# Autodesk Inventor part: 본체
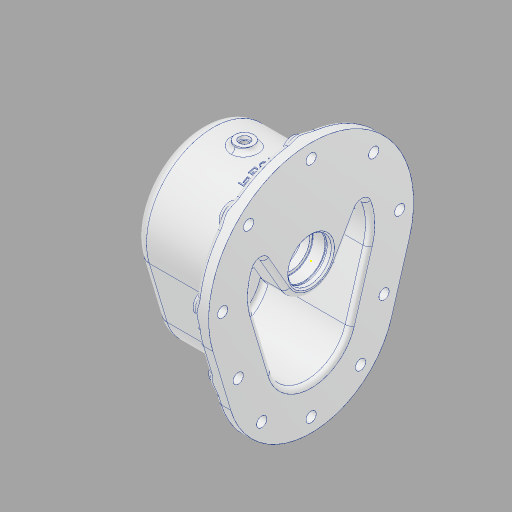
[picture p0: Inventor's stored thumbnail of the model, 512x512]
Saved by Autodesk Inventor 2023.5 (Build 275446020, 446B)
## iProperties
Created: 2026-03
Part Number: 본체
Material: 알루미늄 6061
Document SubType Name: Modeling
Designer: mirae
Density: 2.7 g/cm^3
Appearance: 알루미늄 - 평지
Mass: 810.452 g
Surface Area: 812.392 cm^2
Volume: 300.167 cm^3
Author: mirae
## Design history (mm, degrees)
sketch "스케치1"
  geometry: L1 (0, 0)-(0, -42); L2 (-27, 0)-(-27, -42); L3 (27, -42)-(27, 0); L4 (41.208, -12.286)-(29.708, -50.857); L5 (-41.208, -12.286)-(-29.708, -50.857); A1 r 27 centre (0, 0) between (27, 0) and (-27, 0); A2 r 27 centre (0, -42) between (-27, -42) and (27, -42); A3 r 43 centre (0, 0) between (41.208, -12.286) and (-41.208, -12.286); A4 r 31 centre (0, -42) between (29.708, -50.857) and (-29.708, -50.857); 1 further point
  constraints: 12 end point, 8 point on circle, 8 tangent, 4 centre point, 2 coincident, 1 midpoint, 1 parallel, 1 vertical
  dimensions: "d1" = 54 diameter of A2; "d2" = 86 diameter of A3; "d3" = 62 diameter of A4; "d27" = 42 distance of L1.end L1.start
extrude "돌출1" new body sketch "스케치1" distance "d4" = 71; taper "d5" = 0 deg
extrude "돌출9" join sketch "스케치1" distance "d135" = 71; taper "d136" = 0 deg
sketch "스케치2"
  geometry: L1 (-12.286, 0)-(-12.286, 0) reference; L2 (-12.286, 0)-(-12.286, -71) reference; L3 (-12.286, -71)-(-12.286, -71) reference; L4 (-12.286, 0)-(-12.286, -71) reference; L5 (-12.286, -71)-(43, -71) reference; L6 (43, 0)-(-12.286, 0) reference; L7 (-12.286, -71)-(-50.857, -71) reference; L8 (-50.857, 0)-(-12.286, 0) reference; L9 (0, 0)-(14, 0); L10 (14, 0)-(14, -13); L11 (14, -13)-(0, -13); L12 (0, -13)-(0, 0); L13 (0, -13)-(12, -13); L14 (12, -13)-(12, -59); L15 (12, -59)-(0, -59); L16 (0, -59)-(0, -13); L17 (0, -59)-(14, -59); L18 (14, -59)-(14, -71); L19 (14, -71)-(0, -71); L20 (0, -71)-(0, -59); L21 (0, -5)-(14.7, -5); L22 (14.7, -5)-(14.7, -3.65); L23 (14.7, -3.65)-(0, -3.65); L24 (-50.857, 0)-(-50.857, 0) reference; L25 (-50.857, 0)-(-50.857, -71) reference; L26 (-50.857, -71)-(-50.857, -71) reference; L27 (-50.857, 0)-(-50.857, -71) reference; L28 (-50.857, 0)-(-73, 0) reference; L29 (-12.286, -71)-(-12.286, -71) reference; L30 (-12.286, -71)-(-50.857, -71) reference; L31 (-50.857, -71)-(-50.857, -71) reference; L32 (-50.857, -71)-(-12.286, -71) reference; L33 (-42, 0)-(-42, -71); L34 (-28, -71)-(-42, -71); L35 (-42, -71)-(-42, -59); L36 (-42, -59)-(-28, -59); L37 (-28, -59)-(-28, -71); L38 (-42, -59)-(-30, -59); L39 (-30, -59)-(-30, 0); L40 (-30, 0)-(-42, 0); L41 (-42, 0)-(-42, -59); 12 further points
  constraints: 48 end point, 10 parallel, 8 perpendicular, 7 point on line, 6 horizontal, 1 collinear
  dimensions: "d6" = 28 diameter of L18 L20; "d7" = 24 diameter of L14 L16; "d8" = 71 distance between parallel lines of L9 L19; "d9" = 13 distance of L9.end L10.end; "d10" = 12 distance of L17.end L18.end; "d11" = 1.35 distance of L21.end L22.end; "d12" = 29.4 diameter of L22 L12; "d13" = 8 distance between parallel lines of L21 L11; "d28" = 28 diameter of L37 L35; "d29" = 24 diameter of L39 L41; "d30" = 12 distance of L36.end L34.start; "d31" = 42 distance between parallel lines of L41 L16
  node "투영된 루프1"
  node "투영된 루프2"
  node "투영된 루프5"
revolve "회전1" stored, may be unused: angle "d17" = 360 deg
revolve "회전2" stored, may be unused: angle "d18" = 360 deg
sketch "스케치3"
  geometry: L1 (-41.208, -12.286)-(-29.708, -50.857) reference; L2 (29.708, -50.857)-(41.208, -12.286) reference; L3 (50.101, -62.957)-(63.249, -18.857); L4 (-63.249, -18.857)-(-50.101, -62.957); C1 r 14 at (0, 0) reference; C2 r 54 at (0, -42); A1 r 43 centre (0, 0) between (41.208, -12.286) and (-41.208, -12.286) reference; A2 r 43 centre (0, 0) between (41.208, -12.286) and (-41.208, -12.286) reference; A3 r 31 centre (0, -42) between (-29.708, -50.857) and (29.708, -50.857) reference; A4 r 66 centre (0, 0) between (63.249, -18.857) and (-63.249, -18.857); 7 further points
  constraints: 4 end point, 4 tangent, 2 centre point, 2 coincident, 2 point on circle
  dimensions: "d19" = 132 diameter of A4; "d32" = 108 diameter of C2
extrude "돌출2" join sketch "스케치3" distance "d21" = 9; taper "d22" = 0 deg
sketch "스케치4" dims "d23" = 114
  geometry: L1 (0, 0)-(57, 0); L2 (63.249, -18.857)-(51.749, -57.429) reference; L3 (-51.749, -57.429)-(-63.249, -18.857) reference; L4 (0, -42)-(0, -87); L5 (0, -42)-(-31.82, -73.82); L6 (0, -42)-(-46.957, -42); C1 r 14 at (0, 0) reference; C2 r 12 at (0, -42) reference; A1 r 66 centre (0, 0) between (63.249, -18.857) and (-63.249, -18.857) reference; A2 r 54 centre (0, -42) between (-51.749, -57.429) and (51.749, -57.429) reference; A3 r 45 centre (0, -42) between (0, -87) and (-31.82, -73.82); 5 further points
  constraints: 8 end point, 5 coincident, 2 point on circle, 2 point on line, 1 centre point, 1 horizontal, 1 horizontal alignment, 1 perpendicular, 1 symmetric about line, 1 vertical, 2 other
  dimensions: "d33" = 90 diameter of A3; "d34" = 45 deg angle of L4 L5; "d35" = 9 distance from line of point (-46.957, -42) L3
  node "투영된 루프4"
node "작업 평면1"
sketch "스케치5"
  geometry: C1 r 7 at (-31.82, -73.82); C2 r 7 at (-46.957, -42); C3 r 7 at (46.957, -42); C4 r 7 at (57, 0); 5 further points
  constraints: 4 centre point, 4 coincident
  dimensions: "d37" = 14 diameter of C1; "d38" = 14 diameter of C2; "d39" = 14 diameter of C3; "d40" = 14 diameter of C4
extrude "돌출3" join sketch "스케치5" stored distance "d41" = 9; taper "d42" = 0 deg
extrude "돌출4" join sketch "스케치5" stored distance "d43" = 10; taper "d44" = 0 deg
extrude "돌출5" join sketch "스케치5" stored distance "d48" = 10; taper "d49" = 0 deg
sketch "스케치6"
  geometry: L1 (-41.208, -69.286)-(-29.708, -107.857) reference; L2 (29.708, -107.857)-(41.208, -69.286) reference; L3 (-63.249, -75.857)-(-51.749, -114.429) reference; L4 (51.749, -114.429)-(63.249, -75.857) reference; L5 (63.249, -75.857)-(51.749, -114.429) reference; L6 (-51.749, -114.429)-(-63.249, -75.857) reference; C1 r 7 at (0, 0) reference; C2 r 7 at (40.305, -16.695) reference; C3 r 7 at (57, -57) reference; C4 r 7 at (46.957, -99) reference; C5 r 7 at (31.82, -130.82) reference; C6 r 7 at (0, -144) reference; C7 r 7 at (-31.82, -130.82) reference; C8 r 7 at (-46.957, -99) reference; C9 r 7 at (-57, -57) reference; C10 r 7 at (-40.305, -16.695) reference; C11 r 7 at (0, 0) reference; C12 r 7 at (40.305, -16.695) reference; C13 r 7 at (57, -57) reference; C14 r 7 at (31.82, -130.82) reference; C15 r 7 at (0, -144) reference; C16 r 7 at (-31.82, -130.82) reference; C17 r 7 at (46.957, -99) reference; C18 r 7 at (-46.957, -99) reference; C19 r 7 at (-40.305, -16.695) reference; A1 r 31 centre (0, -99) between (-29.708, -107.857) and (29.708, -107.857) reference; A2 r 43 centre (0, -57) between (41.208, -69.286) and (-41.208, -69.286) reference; A3 r 66 centre (0, -57) between (63.249, -75.857) and (-63.249, -75.857) reference; A4 r 54 centre (0, -99) between (-51.749, -114.429) and (51.749, -114.429) reference; A5 r 66 centre (0, -57) between (63.249, -75.857) and (-63.249, -75.857) reference; A6 r 54 centre (0, -99) between (-51.749, -114.429) and (51.749, -114.429) reference; 11 further points
  constraints: 10 coincident
hole "구멍1" sketch "스케치6" at (-40.305, -16.695), (0, 0), (40.305, -16.695), (57, -57), (46.957, -99), (31.82, -130.82), (0, -144), (-31.82, -130.82), (-46.957, -99), (-57, -57) diameter "d53" = 6.6; stored, may be unused: countersink angle "d57" = 90 deg, drill point angle "d59" = 118 deg; dims "d54" = 6, "d55" = 4, "d56" = 2, "d58" = 8
sketch "스케치7" dims "d60" = 38
  geometry: L1 (0, 0)-(0, 19); L2 (0, -42)-(0, -23); L3 (0, -42)-(0, -61); C1 r 12 at (0, -42) reference; A1 r 19 centre (0, -42) between (0, -23) and (0, -61); 3 further points
  constraints: 6 end point, 4 coincident, 3 vertical, 2 point on circle, 1 centre point, 1 vertical alignment, 2 other
  dimensions: "d61" = 38 diameter of A1
hole "구멍2" sketch "스케치7" diameter "d62" = 3.242; stored, may be unused: countersink angle "d66" = 90 deg, drill point angle "d68" = 118 deg; dims "d63" = 8, "d64" = 4, "d65" = 2, "d67" = 10
hole "구멍4" sketch "스케치7" diameter "d82" = 3.242; stored, may be unused: countersink angle "d86" = 90 deg, drill point angle "d88" = 118 deg; dims "d83" = 8, "d84" = 4, "d85" = 2, "d87" = 10
node "작업 평면2"
sketch "스케치8"
  geometry: L1 (41.208, -12.286)-(29.708, -50.857) reference; L2 (-29.708, -50.857)-(-41.208, -12.286) reference; L3 (36.416, -10.857)-(24.916, -49.429); L4 (-24.916, -49.429)-(-36.416, -10.857); A1 r 43 centre (0, 0) between (41.208, -12.286) and (-41.208, -12.286) reference; A2 r 31 centre (0, -42) between (-29.708, -50.857) and (29.708, -50.857) reference; A3 r 38 centre (0, 0) between (36.416, -10.857) and (-36.416, -10.857); A4 r 26 centre (0, -42) between (-24.916, -49.429) and (24.916, -49.429); 1 further point
  constraints: 4 end point, 4 point on circle, 2 centre point, 3 other
  dimensions: "d93" = 5 radial gap between concentric circles of A1 A3
extrude "돌출6" cut sketch "스케치8" distance "d94" = 37; taper "d95" = 0 deg
node "작업 평면4"
sketch "스케치9"
  geometry: L1 (24.916, -49.429)-(36.416, -10.857) reference; L2 (-36.416, -10.857)-(-24.916, -49.429) reference; L3 (16.454, -9.5)-(32.909, 19); L4 (-16.454, -9.5)-(-32.909, 19); L5 (0, 0)-(0, 26.424); A1 r 38 centre (0, 0) between (36.416, -10.857) and (-36.416, -10.857) reference; A2 r 38 centre (0, 0) between (36.416, -10.857) and (-36.416, -10.857) reference; A3 r 26 centre (0, -42) between (-24.916, -49.429) and (24.916, -49.429) reference; A4 r 19 centre (0, 0) between (16.454, -9.5) and (-16.454, -9.5); 5 further points
  constraints: 6 end point, 4 point on circle, 2 coincident, 1 centre point, 1 tangent, 1 vertical, 1 other
  dimensions: "d98" = 38 diameter of A4; "d99" = 30 deg angle of L5 L4
extrude "돌출7" cut sketch "스케치9" distance "d100" = 18; taper "d101" = 0 deg
sketch "스케치10"
  geometry: 1 further point
node "작업 평면5"
node "작업 평면6"
sketch "스케치11"
  geometry: L1 (-14, 0)-(14, 0) reference; L2 (0, 0)-(0, -43); C1 r 6 at (0, -43); 1 further point
  constraints: 2 coincident, 2 end point, 1 centre point, 1 vertical
  dimensions: "d103" = 43 distance of L2.start L2.end; "d104" = 12 diameter of C1
extrude "돌출8" join sketch "스케치11" stored distance "d105" = 18; taper "d106" = 0 deg
sketch "스케치12"
  geometry: C1 r 6 at (0, 0) reference; 2 further points
  constraints: 1 coincident
hole "구멍5" sketch "스케치12" at (0, 0) diameter "d107" = 7; stored, may be unused: countersink angle "d111" = 90 deg, drill point angle "d113" = 0 deg; dims "d108" = 8, "d109" = 4, "d110" = 2, "d112" = 2
sketch "스케치14"
  geometry: C1 r 3.5 at (0, 0) reference; 2 further points
  constraints: 1 coincident
hole "구멍6" sketch "스케치14" at (0, 0) diameter "d114" = 5.1881; stored, may be unused: countersink angle "d118" = 90 deg, drill point angle "d120" = 0 deg; dims "d115" = 12, "d116" = 4, "d117" = 2, "d119" = 22.931
node "작업 평면8"
  node "작업 평면7"
chamfer "모따기1" distance "d122" = 1; stored, may be unused: second distance "d123" = 2, angle "d124" = 45 deg
fillet "모깎기2" dims "d126" = 3
fillet "모깎기3" dims "d127" = 3
fillet "모깎기4" dims "d128" = 3
fillet "모깎기5" dims "d129" = 8
fillet "모깎기6" dims "d130" = 3
fillet "모깎기7" dims "d131" = 3
node "작업 평면9"
sketch "스케치15"
  geometry: L1 (15, 0)-(-15, 0) reference; 1 further point
sketch "스케치16"
  geometry: L1 (66, 0)-(-66, 0) reference; 6 further points
  constraints: 2 midpoint, 1 vertical alignment, 1 other
  dimensions: "d132" = 25 distance of point (0, 0) point (0, -25)
feature "엠보싱1" sketch "스케치16" dims "d133" = 0.5, "d134" = 0
fillet "모깎기8" dims "d137" = 0.3
fillet "모깎기9" dims "d138" = 0.3
node "솔리드1"
pattern_circular "원형 패턴1" dims angle "d46" = 90 deg
pattern_circular "원형 패턴2" dims angle "d51" = 180 deg
pattern_circular "원형 패턴3" dims angle "d70" = 360 deg
pattern_circular "원형 패턴5" dims angle "d90" = 360 deg
mirror "미러1"
node "투영된 루프3"
node "투영된 루프6"
node "투영된 루프7"
node "투영된 루프8"
node "투영된 루프9"
feature "A9D066F2-1C7D-4E18-AEED-F7BC21143FA4" dims "d53" = 6.6, "d54" = 6, "d55" = 4, "d56" = 2, "d57" = 90 deg, "d58" = 8, "d59" = 118 deg
other parameters: "d36" = 3, "d92" = -55, "d97" = -18, "d102" = 3
